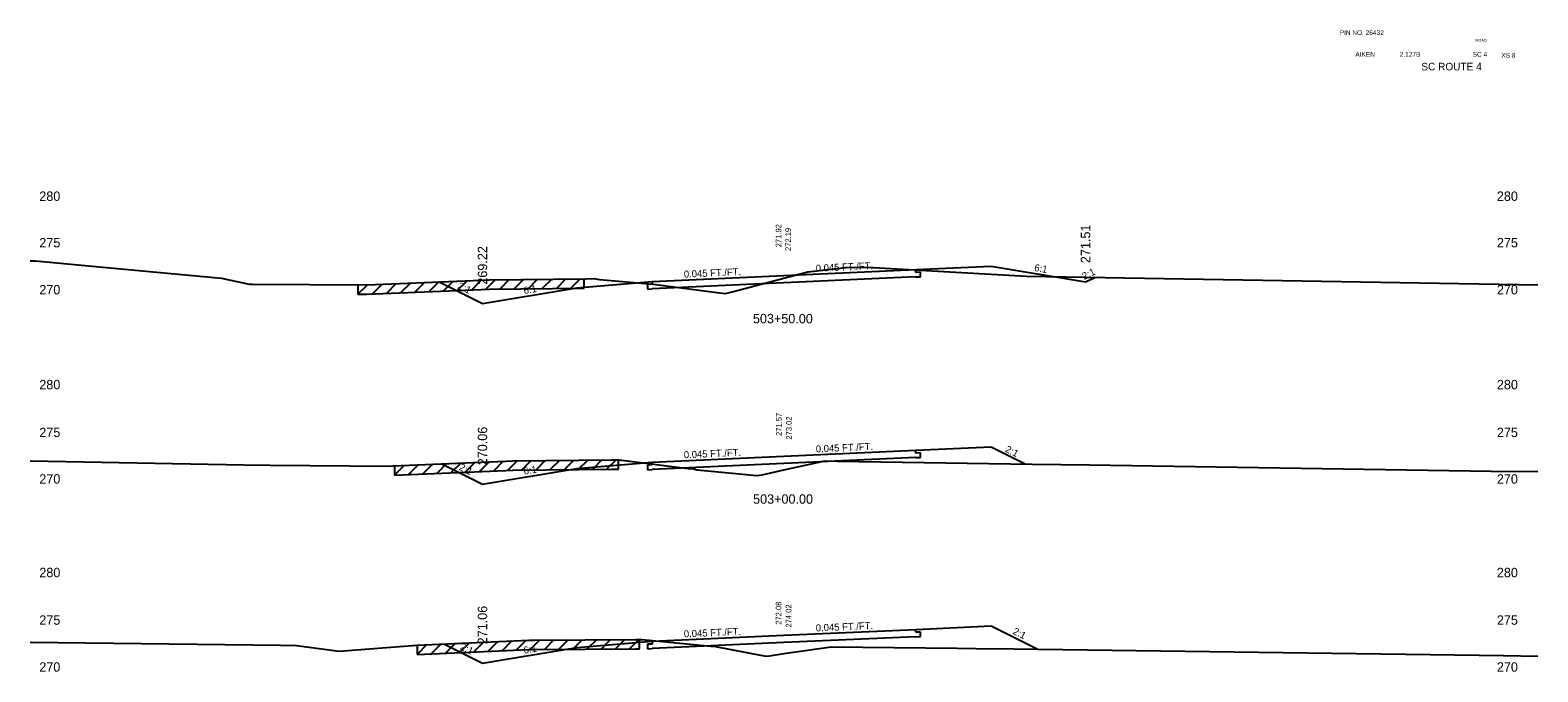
# Model space of a CAD drawing. Extents: x 883 to 1160, y 1002 to 4323.
# Drawn here: x 1000 to 1160, y 1840.1 to 1908.2 of the extents above; entities that cross this region are included whole.
import ezdxf

# ---------------------------------------------------------------- set-up
doc = ezdxf.new("R2010")
doc.units = 0
for name, color, linetype in [('Level 1', 7, 'Continuous'), ('Level 10', 7, 'Continuous'), ('Level 11', 7, 'Continuous'), ('Level 12', 7, 'Continuous'), ('Level 3', 7, 'Continuous'), ('Level 32', 7, 'Continuous'), ('Level 33', 7, 'Continuous'), ('Level 59', 7, 'Continuous'), ('Level 6', 7, 'Continuous'), ('Level 60', 7, 'Continuous'), ('Level 61', 7, 'Continuous'), ('Level 7', 7, 'Continuous')]:
    doc.layers.add(name, color=color, linetype=linetype)

msp = doc.modelspace()

# ---------------------------------------------------------------- linework, layer by layer
at = {"layer": 'Level 11'}
for p, q in [((1094, 1882.52), (1094, 1882.82)), ((1094.5, 1882.54), (1094, 1882.52)), ((1094, 1882.04), (1094.5, 1882.06)), ((1094.5, 1882.06), (1094.5, 1882.54)), ((1066, 1881.26), (1065.5, 1881.24)), ((1065.5, 1881.24), (1065.5, 1880.76)), ((1065.5, 1880.76), (1066, 1880.78)), ((1066, 1881.56), (1066, 1881.26)), ((1094, 1863.35), (1094, 1863.65)), ((1094.5, 1863.37), (1094, 1863.35)), ((1094, 1862.87), (1094.5, 1862.89)), ((1094.5, 1862.89), (1094.5, 1863.37)), ((1066, 1862.09), (1065.5, 1862.07)), ((1065.5, 1862.07), (1065.5, 1861.59)), ((1065.5, 1861.59), (1066, 1861.61)), ((1066, 1862.39), (1066, 1862.09)), ((1066, 1843.39), (1066, 1843.09)), ((1094, 1844.35), (1094, 1844.65)), ((1094.5, 1844.37), (1094, 1844.35)), ((1094, 1843.87), (1094.5, 1843.89)), ((1094.5, 1843.89), (1094.5, 1844.37)), ((1066, 1843.09), (1065.5, 1843.07)), ((1065.5, 1843.07), (1065.5, 1842.59)), ((1065.5, 1842.59), (1066, 1842.61))]:
    msp.add_line(p, q, dxfattribs=at)
at = {"layer": 'Level 12'}
for p, q in [((1094, 1882.04), (1080, 1881.41)), ((1080, 1881.41), (1066, 1880.78)), ((1094, 1862.87), (1080, 1862.24)), ((1080, 1862.24), (1066, 1861.61)), ((1080, 1843.24), (1066, 1842.61)), ((1094, 1843.87), (1080, 1843.24))]:
    msp.add_line(p, q, dxfattribs=at)
at = {"layer": 'Level 59'}
for p, q in [((1066, 1881.56), (1080, 1882.19)), ((1080, 1882.19), (1094, 1882.82)), ((1066, 1862.39), (1080, 1863.02)), ((1080, 1863.02), (1094, 1863.65)), ((1066, 1843.39), (1080, 1844.02)), ((1080, 1844.02), (1094, 1844.65))]:
    msp.add_line(p, q, dxfattribs=at)
at = {"layer": 'Level 6'}
for p, q in [((1094, 1882.82), (1102, 1883.18)), ((1058, 1880.89), (1066, 1881.56)), ((1094, 1863.65), (1102, 1864.01)), ((1058, 1861.72), (1066, 1862.39)), ((1094, 1844.65), (1102, 1845.01)), ((1058, 1842.72), (1066, 1843.39))]:
    msp.add_line(p, q, dxfattribs=at)
at = {"layer": 'Level 60'}
for p, q in [((1000, 1883.75), (1000.01, 1883.75)), ((1000.01, 1883.75), (1000.56, 1883.75)), ((1000.56, 1883.75), (1008.09, 1883.05)), ((1008.09, 1883.05), (1020.31, 1881.92)), ((1020.31, 1881.92), (1023.23, 1881.28)), ((1035.72, 1881.2), (1047.89, 1881.7)), ((1047.89, 1881.7), (1048.71, 1881.73)), ((1048.71, 1881.73), (1058.96, 1881.85)), ((1058.96, 1881.85), (1059.81, 1881.86)), ((1059.81, 1881.86), (1060.41, 1881.78)), ((1060.41, 1881.78), (1066.11, 1881.27)), ((1074.5, 1880.46), (1080, 1881.92)), ((1080, 1881.92), (1082.53, 1882.59)), ((1082.53, 1882.59), (1086.9, 1883.09)), ((1086.9, 1883.09), (1089.46, 1883.05)), ((1089.46, 1883.05), (1105.75, 1882.12)), ((1105.75, 1882.12), (1112.01, 1882.01)), ((1112.01, 1882.01), (1160, 1881.21)), ((1023.23, 1881.28), (1023.61, 1881.28)), ((1023.61, 1881.28), (1035.72, 1881.2)), ((1066.11, 1881.27), (1073.14, 1880.37)), ((1073.14, 1880.37), (1073.79, 1880.3)), ((1073.79, 1880.3), (1074.5, 1880.46)), ((1000, 1862.53), (1022.69, 1862.11)), ((1038.54, 1862), (1050.49, 1862.5)), ((1050.49, 1862.5), (1051.21, 1862.53)), ((1051.21, 1862.53), (1061.72, 1862.63)), ((1061.72, 1862.63), (1062.5, 1862.63)), ((1062.5, 1862.63), (1069.84, 1861.72)), ((1080, 1861.57), (1084.36, 1862.53)), ((1084.36, 1862.53), (1085.69, 1862.51)), ((1085.69, 1862.51), (1106.34, 1862.19)), ((1022.69, 1862.11), (1025.48, 1862.06)), ((1025.48, 1862.06), (1038.11, 1861.97)), ((1038.11, 1861.97), (1038.54, 1862)), ((1069.84, 1861.72), (1070.41, 1861.67)), ((1070.41, 1861.67), (1070.8, 1861.59)), ((1070.8, 1861.59), (1077.12, 1860.98)), ((1077.12, 1860.98), (1077.7, 1861.06)), ((1077.7, 1861.06), (1080, 1861.57)), ((1106.34, 1862.19), (1112.41, 1862.11)), ((1112.41, 1862.11), (1155.04, 1861.43)), ((1155.04, 1861.43), (1160, 1861.39)), ((1000, 1843.3), (1026.58, 1842.98)), ((1041.04, 1842.99), (1052.91, 1843.5)), ((1052.91, 1843.5), (1053.54, 1843.52)), ((1053.54, 1843.52), (1064.28, 1843.57)), ((1064.28, 1843.57), (1064.94, 1843.58)), ((1064.94, 1843.58), (1072.25, 1842.87)), ((1026.58, 1842.98), (1028.25, 1842.94)), ((1028.25, 1842.94), (1032.8, 1842.34)), ((1032.8, 1842.34), (1041.04, 1842.99)), ((1072.25, 1842.87), (1072.73, 1842.83)), ((1072.73, 1842.83), (1073.08, 1842.75)), ((1073.08, 1842.75), (1078.07, 1841.8)), ((1078.07, 1841.8), (1078.45, 1841.85)), ((1078.45, 1841.85), (1080, 1842.08)), ((1080, 1842.08), (1085, 1842.79)), ((1085, 1842.79), (1098.36, 1842.67)), ((1098.36, 1842.67), (1100.35, 1842.61)), ((1100.35, 1842.61), (1104.38, 1842.59)), ((1104.38, 1842.59), (1156.36, 1841.89)), ((1156.36, 1841.89), (1160, 1841.82))]:
    msp.add_line(p, q, dxfattribs=at)
at = {"layer": 'Level 61'}
for p, q in [((1046.37, 1881.64), (1045.32, 1880.59)), ((1047.87, 1881.7), (1046.82, 1880.65)), ((1049.35, 1881.74), (1048.33, 1880.72)), ((1050.85, 1881.76), (1049.83, 1880.74)), ((1052.35, 1881.77), (1051.34, 1880.76)), ((1053.85, 1881.79), (1052.84, 1880.78)), ((1055.36, 1881.81), (1054.34, 1880.8)), ((1056.86, 1881.83), (1055.85, 1880.81)), ((1058.37, 1881.84), (1057.35, 1880.83)), ((1058.78, 1880.85), (1058.78, 1881.85)), ((1035.79, 1881.2), (1034.79, 1880.2)), ((1034.79, 1881.2), (1034.79, 1880.2)), ((1034.79, 1880.2), (1035.72, 1880.2)), ((1035.72, 1880.2), (1047.89, 1880.7)), ((1037.34, 1881.26), (1036.3, 1880.22)), ((1038.85, 1881.33), (1037.8, 1880.28)), ((1040.35, 1881.39), (1039.3, 1880.35)), ((1041.85, 1881.45), (1040.81, 1880.41)), ((1043.36, 1881.51), (1042.31, 1880.47)), ((1044.86, 1881.57), (1043.82, 1880.53)), ((1047.89, 1880.7), (1048.71, 1880.73)), ((1048.71, 1880.73), (1058.78, 1880.85)), ((1048.7, 1862.42), (1047.66, 1861.38)), ((1050.2, 1862.48), (1049.16, 1861.44)), ((1051.69, 1862.53), (1050.66, 1861.5)), ((1053.17, 1862.55), (1052.16, 1861.54)), ((1054.67, 1862.56), (1053.66, 1861.55)), ((1056.17, 1862.58), (1055.16, 1861.57)), ((1057.68, 1862.59), (1056.66, 1861.58)), ((1059.18, 1862.61), (1058.17, 1861.6)), ((1060.68, 1862.62), (1059.67, 1861.61)), ((1062.18, 1862.63), (1061.17, 1861.63)), ((1062.42, 1861.63), (1062.42, 1862.63)), ((1039.69, 1862.05), (1038.65, 1861.01)), ((1038.65, 1862.01), (1038.65, 1861.01)), ((1038.65, 1861.01), (1050.49, 1861.5)), ((1041.19, 1862.11), (1040.15, 1861.07)), ((1042.7, 1862.17), (1041.65, 1861.13)), ((1044.2, 1862.24), (1043.15, 1861.19)), ((1045.7, 1862.3), (1044.65, 1861.25)), ((1047.2, 1862.36), (1046.16, 1861.32)), ((1050.49, 1861.5), (1051.21, 1861.53)), ((1051.21, 1861.53), (1061.72, 1861.63)), ((1061.72, 1861.63), (1062.42, 1861.63)), ((1046.61, 1843.23), (1045.57, 1842.18)), ((1048.12, 1843.29), (1047.07, 1842.25)), ((1049.62, 1843.36), (1048.57, 1842.31)), ((1051.12, 1843.42), (1050.08, 1842.37)), ((1052.62, 1843.48), (1051.58, 1842.44)), ((1054.1, 1843.53), (1053.08, 1842.5)), ((1055.59, 1843.53), (1054.58, 1842.53)), ((1057.09, 1843.54), (1056.09, 1842.54)), ((1058.59, 1843.55), (1057.59, 1842.54)), ((1060.1, 1843.55), (1059.09, 1842.55)), ((1061.6, 1843.56), (1060.59, 1842.55)), ((1063.1, 1843.57), (1062.09, 1842.56)), ((1064.6, 1843.57), (1063.6, 1842.57)), ((1064.68, 1842.57), (1064.68, 1843.57)), ((1042.11, 1843.03), (1041.06, 1841.99)), ((1041.06, 1842.99), (1041.06, 1841.99)), ((1041.06, 1841.99), (1052.91, 1842.5)), ((1043.61, 1843.1), (1042.56, 1842.05)), ((1045.11, 1843.16), (1044.07, 1842.12)), ((1052.91, 1842.5), (1053.54, 1842.52)), ((1053.54, 1842.52), (1064.28, 1842.57)), ((1064.28, 1842.57), (1064.68, 1842.57))]:
    msp.add_line(p, q, dxfattribs=at)
at = {"layer": 'Level 7'}
for p, q in [((1102, 1883.18), (1112, 1881.51)), ((1112, 1881.51), (1112.97, 1882)), ((1043.42, 1881.51), (1048, 1879.22)), ((1048, 1879.22), (1058, 1880.89)), ((1102, 1864.01), (1105.61, 1862.2)), ((1043.69, 1862.21), (1048, 1860.06)), ((1048, 1860.06), (1058, 1861.72)), ((1102, 1845.01), (1106.92, 1842.55)), ((1043.9, 1843.11), (1048, 1841.06)), ((1048, 1841.06), (1058, 1842.72))]:
    msp.add_line(p, q, dxfattribs=at)

# ---------------------------------------------------------------- texts
at = {"layer": 'Level 1'}
for s, height, p in [('PIN NO. 26432', 0.5, (1138.97, 1907.72)), ('AIKEN', 0.5, (1140.64, 1905.41)), (' 2.127B', 0.5, (1145.15, 1905.41)), ('SC 4', 0.5, (1153.09, 1905.41)), ('XS 8', 0.5, (1156.12, 1905.31)), ('SC ROUTE 4', 0.8, (1147.63, 1903.96)), ('503+50.00', 1, (1076.7, 1877.12)), ('503+00.00', 1, (1076.72, 1857.98))]:
    msp.add_text(s, height=height, dxfattribs=at).set_placement(p)
at = {"layer": 'Level 10'}
for s, p in [('271.92', (1079.72, 1885.19)), ('271.57', (1079.76, 1865.17)), ('272.08', (1079.72, 1845.14))]:
    msp.add_text(s, height=0.6, rotation=90, dxfattribs=at).set_placement(p)
at = {"layer": 'Level 3'}
for s, height, p in [('ROAD', 0.3, (1153.38, 1906.99)), (' 280', 1, (1000.6, 1890.11)), (' 280', 1, (1155.28, 1890.11)), (' 275', 1, (1000.6, 1885.18)), (' 275', 1, (1155.28, 1885.18)), (' 270', 1, (1000.6, 1880.19)), (' 270', 1, (1155.28, 1880.19)), (' 280', 1, (1000.6, 1870.12)), (' 280', 1, (1155.28, 1870.12)), (' 275', 1, (1000.6, 1865.05)), (' 275', 1, (1155.28, 1865.05)), (' 270', 1, (1000.6, 1860.11)), (' 270', 1, (1155.28, 1860.11)), (' 280', 1, (1000.6, 1850.18)), (' 280', 1, (1155.28, 1850.18)), (' 275', 1, (1000.6, 1845.14)), (' 275', 1, (1155.28, 1845.14)), (' 270', 1, (1000.6, 1840.16)), (' 270', 1, (1155.28, 1840.16))]:
    msp.add_text(s, height=height, dxfattribs=at).set_placement(p)
at = {"layer": 'Level 32'}
for s, rotation, p in [('0.045 FT./FT.', 2.5766, (1083.39, 1882.59)), ('6:1', 350.5377, (1106.52, 1882.68)), ('0.045 FT./FT.', 2.5766, (1069.39, 1881.96)), ('2:1', 26.5651, (1111.87, 1881.72)), ('2:1', 333.435, (1045.31, 1880.85)), ('6:1', 9.4623, (1052.43, 1880.22)), ('0.045 FT./FT.', 2.5766, (1083.39, 1863.42)), ('2:1', 333.435, (1103.41, 1863.52)), ('0.045 FT./FT.', 2.5766, (1069.39, 1862.79)), ('2:1', 333.435, (1045.45, 1861.61)), ('6:1', 9.4623, (1052.43, 1861.05)), ('0.045 FT./FT.', 2.5766, (1069.39, 1843.79)), ('0.045 FT./FT.', 2.5766, (1083.39, 1844.42)), ('2:1', 333.435, (1104.21, 1844.2)), ('2:1', 333.435, (1045.55, 1842.56)), ('6:1', 9.4623, (1052.43, 1842.05))]:
    msp.add_text(s, height=0.75, rotation=rotation, dxfattribs=at).set_placement(p)
at = {"layer": 'Level 33'}
for s, p in [('271.51', (1112.5, 1883.51)), ('269.22', (1048.5, 1881.22)), ('270.06', (1048.5, 1862.06)), ('271.06', (1048.5, 1843.06))]:
    msp.add_text(s, height=1, rotation=90, dxfattribs=at).set_placement(p)
at = {"layer": 'Level 59'}
for s, p in [(' 272.19', (1080.74, 1884.57)), (' 273.02', (1080.82, 1864.56)), (' 274.02', (1080.79, 1844.62))]:
    msp.add_text(s, height=0.6, rotation=90, dxfattribs=at).set_placement(p)

doc.saveas('drawing.dxf')
